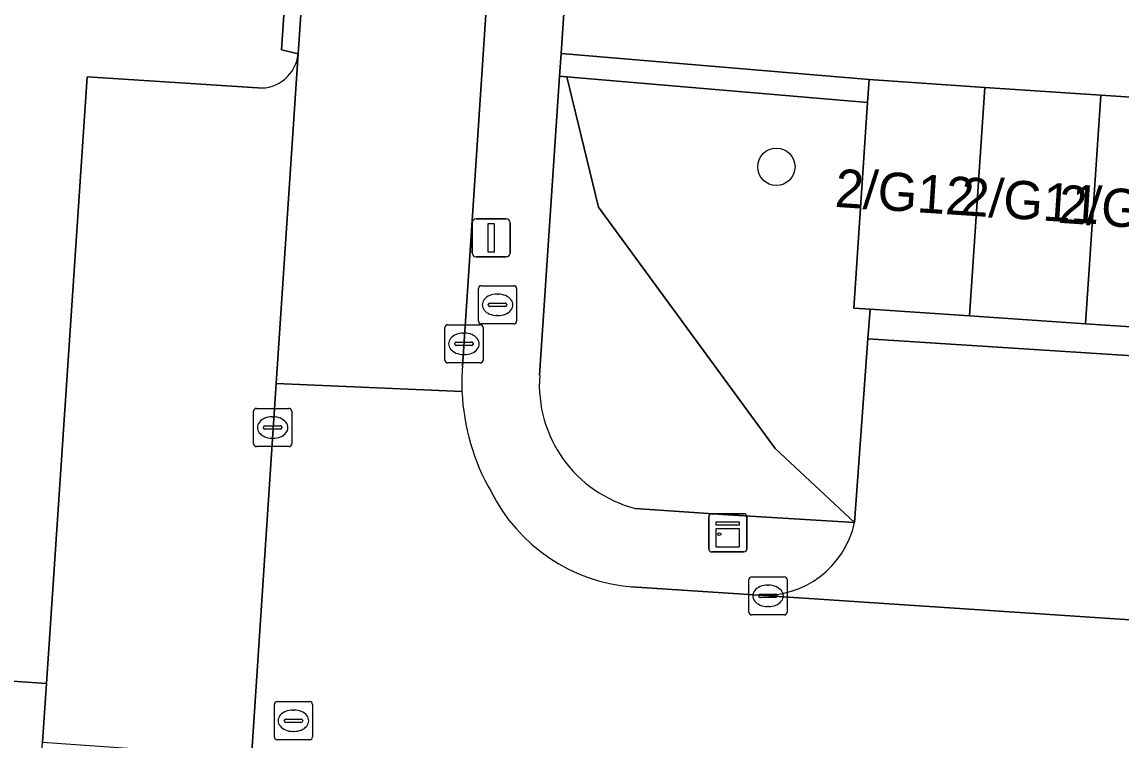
# Model space of a CAD drawing. Extents: x 161848 to 162726, y 385382 to 386521.
# Drawn here: x 161953.99 to 161982.82, y 386006.55 to 386025.38 of the extents above; entities that cross this region are included whole.
import ezdxf

# ---------------------------------------------------------------- set-up
doc = ezdxf.new("R2010")
doc.units = 0
for name, color, linetype in [('IMGEO_Boom', 7, 'Continuous'), ('IMGEO_Brandkraan', 7, 'Continuous'), ('IMGEO_Erf', 7, 'Continuous'), ('IMGEO_Groenvoorziening', 7, 'Continuous'), ('IMGEO_Haag', 7, 'Continuous'), ('IMGEO_Kast', 7, 'Continuous'), ('IMGEO_Kolk', 7, 'Continuous'), ('IMGEO_Lichtmast', 7, 'Continuous'), ('IMGEO_Pand', 7, 'Continuous'), ('IMGEO_Pand_nummerreeks', 7, 'Continuous'), ('IMGEO_Parkeervlak_open', 7, 'Continuous'), ('IMGEO_Rijbaan_lokaal_open', 7, 'Continuous'), ('IMGEO_Rioolput', 7, 'Continuous'), ('IMGEO_Verkeerseiland_open', 7, 'Continuous'), ('IMGEO_Voetpad_open', 7, 'Continuous')]:
    doc.layers.add(name, color=color, linetype=linetype)

msp = doc.modelspace()

# ---------------------------------------------------------------- linework, layer by layer
at = {"layer": 'IMGEO_Boom'}
msp.add_circle((161973.762, 386021.589), 0.489, dxfattribs=at)
at = {"layer": 'IMGEO_Brandkraan'}
for p, q in [((161965.952, 386017.547), (161965.952, 386018.399)), ((161966.027, 386018.473), (161966.879, 386018.473)), ((161966.953, 386018.399), (161966.953, 386017.547)), ((161966.254, 386018.016), (161966.652, 386018.016)), ((161966.44, 386018.253), (161966.465, 386018.253)), ((161966.211, 386017.967), (161966.211, 386017.979)), ((161966.649, 386017.93), (161966.251, 386017.93)), ((161966.695, 386017.979), (161966.695, 386017.967)), ((161966.879, 386017.473), (161966.027, 386017.473)), ((161966.463, 386017.693), (161966.438, 386017.693))]:
    msp.add_line(p, q, dxfattribs=at)
for points in [[(161965.952, 386017.547), (161965.952, 386018.399)], [(161966.027, 386018.473), (161966.879, 386018.473)], [(161966.953, 386018.399), (161966.953, 386017.547)], [(161966.879, 386017.473), (161966.027, 386017.473)]]:
    msp.add_lwpolyline(points, dxfattribs=at)
for centre, radius, start, end in [((161966.029, 386018.397), 0.0765, 91.552, 178.448), ((161966.029, 386018.397), 0.0765, 91.552, 178.448), ((161966.877, 386018.397), 0.0765, 1.552, 88.448), ((161966.877, 386018.397), 0.0765, 1.552, 88.448), ((161966.251, 386017.976), 0.0403, 85.8775, 175.7526), ((161966.656, 386017.978), 0.0386, 1.7309, 96.639), ((161966.248, 386017.966), 0.0366, 178.938, 274.7102), ((161966.652, 386017.973), 0.043, 264.8664, 352.4533), ((161966.029, 386017.549), 0.0765, 181.552, 268.448), ((161966.029, 386017.549), 0.0765, 181.552, 268.448), ((161966.877, 386017.549), 0.0765, 271.552, 358.448), ((161966.877, 386017.549), 0.0765, 271.552, 358.448)]:
    msp.add_arc(centre, radius, start, end, dxfattribs=at)
for centre, major_axis, ratio, start_param, end_param in [((161966.439, 386017.973), (-0.387, 0.002), 0.722429, 4.712389, 7.853982), ((161966.464, 386017.973), (-0.39, 0.002), 0.717154, 1.570796, 4.712389)]:
    msp.add_ellipse(centre, major_axis=major_axis, ratio=ratio, start_param=start_param, end_param=end_param, dxfattribs=at)
at = {"layer": 'IMGEO_Erf'}
msp.add_lwpolyline([(161973.071, 386098.474), (161968.121, 386024.56), (161976.193, 386023.874), (161979.229, 386023.67), (161982.266, 386023.466), (161985.302, 386023.262), (161988.338, 386023.059), (161991.375, 386022.855), (161994.411, 386022.651), (161994.699, 386027.79)], dxfattribs=at)
at = {"layer": 'IMGEO_Groenvoorziening'}
for points in [[(161943.048, 386128.27), (161942.06, 386112.903), (161936.093, 386020.157), (161930.341, 386020.536), (161932.562, 386055.006), (161928.781, 386055.255), (161926.803, 386025.337), (161926.763, 386019.638), (161926.902, 386014.485), (161927.435, 386010.565), (161928.183, 386010.091), (161929.03, 386009.835), (161934.854, 386009.415), (161936.618, 386009.293), (161937.077, 386015.948), (161946.906, 386015.3), (161946.445, 386008.616), (161954.625, 386008.052), (161955.692, 386023.943), (161960.168, 386023.656)], [(161961.227, 386024.551), (161960.785, 386024.65), (161965.608, 386096.137), (161966.064, 386096.102)], [(161969.103, 386020.53), (161968.271, 386023.945), (161968.081, 386023.961), (161967.557, 386016.132)], [(161970.064, 386012.641), (161972.489, 386012.469), (161975.811, 386012.268), (161973.729, 386014.209), (161969.103, 386020.53)]]:
    msp.add_lwpolyline(points, dxfattribs=at)
for points in [[(161968.121, 386024.56), (161968.081, 386023.961), (161968.271, 386023.945), (161976.153, 386023.275), (161976.193, 386023.874)], [(161976.153, 386023.275), (161968.271, 386023.945), (161969.103, 386020.53), (161973.729, 386014.209), (161975.811, 386012.268), (161976.163, 386017.082), (161976.22, 386017.858), (161975.791, 386017.887)]]:
    msp.add_lwpolyline(points, close=True, dxfattribs=at)
for centre, radius, start, end in [((161960.241, 386024.644), 0.99, 265.7686, 354.6362), ((161970.893, 386015.882), 3.345, 175.7137, 255.653)]:
    msp.add_arc(centre, radius, start, end, dxfattribs=at)
at = {"layer": 'IMGEO_Haag'}
msp.add_lwpolyline([(161968.121, 386024.56), (161968.081, 386023.961), (161968.271, 386023.945), (161976.153, 386023.275), (161976.193, 386023.874)], close=True, dxfattribs=at)
at = {"layer": 'IMGEO_Kast'}
for p, q in [((161971.988, 386011.575), (161971.988, 386012.416)), ((161971.988, 386012.416), (161971.988, 386011.575)), ((161972.063, 386012.5), (161972.904, 386012.5)), ((161972.904, 386012.5), (161972.063, 386012.5)), ((161972.988, 386012.425), (161972.988, 386011.584)), ((161972.988, 386011.584), (161972.988, 386012.425)), ((161972.913, 386011.5), (161972.072, 386011.5)), ((161972.072, 386011.5), (161972.913, 386011.5))]:
    msp.add_line(p, q, dxfattribs=at)
for points in [[(161972.183, 386012.29), (161972.783, 386012.29), (161972.783, 386012.205), (161972.183, 386012.205), (161972.183, 386012.29)], [(161972.183, 386012.115), (161972.783, 386012.115), (161972.783, 386011.626), (161972.183, 386011.626), (161972.183, 386012.115)]]:
    msp.add_lwpolyline(points, dxfattribs=at)
msp.add_circle((161972.267, 386011.964), 0.0377, dxfattribs=at)
for centre, start, end in [((161972.066, 386012.422), 92.4484, 184.2845), ((161972.066, 386012.422), 92.4484, 184.2845), ((161972.91, 386012.422), 2.4484, 94.2845), ((161972.91, 386012.422), 2.4484, 94.2845), ((161972.066, 386011.578), 182.4484, 274.2845), ((161972.066, 386011.578), 182.4484, 274.2845), ((161972.91, 386011.578), 272.4484, 4.2845), ((161972.91, 386011.578), 272.4484, 4.2845)]:
    msp.add_arc(centre, 0.0779, start, end, dxfattribs=at)
at = {"layer": 'IMGEO_Kolk'}
for p, q in [((161965.146, 386017.452), (161965.998, 386017.452)), ((161965.071, 386016.526), (161965.071, 386017.378)), ((161965.559, 386017.232), (161965.584, 386017.232)), ((161966.072, 386017.378), (161966.072, 386016.526)), ((161965.33, 386016.946), (161965.33, 386016.958)), ((161965.768, 386016.909), (161965.37, 386016.909)), ((161965.373, 386016.995), (161965.771, 386016.995)), ((161965.814, 386016.958), (161965.814, 386016.946)), ((161965.582, 386016.672), (161965.557, 386016.672)), ((161965.998, 386016.452), (161965.146, 386016.452)), ((161960.056, 386014.333), (161960.056, 386015.185)), ((161960.131, 386015.259), (161960.983, 386015.259)), ((161961.057, 386015.185), (161961.057, 386014.333)), ((161960.544, 386015.039), (161960.569, 386015.039)), ((161960.315, 386014.753), (161960.315, 386014.765)), ((161960.753, 386014.716), (161960.355, 386014.716)), ((161960.358, 386014.802), (161960.756, 386014.802)), ((161960.799, 386014.765), (161960.799, 386014.753)), ((161960.983, 386014.259), (161960.131, 386014.259)), ((161960.567, 386014.479), (161960.542, 386014.479)), ((161973.118, 386010.849), (161973.97, 386010.849)), ((161973.043, 386009.923), (161973.043, 386010.775)), ((161973.531, 386010.629), (161973.556, 386010.629)), ((161974.044, 386010.775), (161974.044, 386009.923)), ((161973.302, 386010.343), (161973.302, 386010.355)), ((161973.74, 386010.306), (161973.342, 386010.306)), ((161973.345, 386010.392), (161973.743, 386010.392)), ((161973.786, 386010.355), (161973.786, 386010.343)), ((161973.554, 386010.069), (161973.529, 386010.069)), ((161973.97, 386009.849), (161973.118, 386009.849))]:
    msp.add_line(p, q, dxfattribs=at)
for points in [[(161965.146, 386017.452), (161965.998, 386017.452)], [(161965.071, 386016.526), (161965.071, 386017.378)], [(161966.072, 386017.378), (161966.072, 386016.526)], [(161965.998, 386016.452), (161965.146, 386016.452)], [(161960.056, 386014.333), (161960.056, 386015.185)], [(161960.131, 386015.259), (161960.983, 386015.259)], [(161961.057, 386015.185), (161961.057, 386014.333)], [(161960.983, 386014.259), (161960.131, 386014.259)], [(161973.118, 386010.849), (161973.97, 386010.849)], [(161973.043, 386009.923), (161973.043, 386010.775)], [(161974.044, 386010.775), (161974.044, 386009.923)], [(161973.97, 386009.849), (161973.118, 386009.849)]]:
    msp.add_lwpolyline(points, dxfattribs=at)
for centre, radius, start, end in [((161965.148, 386017.376), 0.0765, 91.552, 178.448), ((161965.148, 386017.376), 0.0765, 91.552, 178.448), ((161965.996, 386017.376), 0.0765, 1.552, 88.448), ((161965.996, 386017.376), 0.0765, 1.552, 88.448), ((161965.37, 386016.955), 0.0403, 85.8775, 175.7526), ((161965.367, 386016.945), 0.0366, 178.938, 274.7102), ((161965.771, 386016.952), 0.043, 264.8664, 352.4533), ((161965.775, 386016.957), 0.0386, 1.7309, 96.639), ((161965.148, 386016.528), 0.0765, 181.552, 268.448), ((161965.148, 386016.528), 0.0765, 181.552, 268.448), ((161965.996, 386016.528), 0.0765, 271.552, 358.448), ((161965.996, 386016.528), 0.0765, 271.552, 358.448), ((161960.133, 386015.183), 0.0765, 91.552, 178.448), ((161960.133, 386015.183), 0.0765, 91.552, 178.448), ((161960.981, 386015.183), 0.0765, 1.552, 88.448), ((161960.981, 386015.183), 0.0765, 1.552, 88.448), ((161960.355, 386014.762), 0.0403, 85.8775, 175.7526), ((161960.352, 386014.752), 0.0366, 178.938, 274.7102), ((161960.756, 386014.759), 0.043, 264.8664, 352.4533), ((161960.76, 386014.764), 0.0386, 1.7309, 96.639), ((161960.133, 386014.335), 0.0765, 181.552, 268.448), ((161960.133, 386014.335), 0.0765, 181.552, 268.448), ((161960.981, 386014.335), 0.0765, 271.552, 358.448), ((161960.981, 386014.335), 0.0765, 271.552, 358.448), ((161973.12, 386010.773), 0.0765, 91.552, 178.448), ((161973.12, 386010.773), 0.0765, 91.552, 178.448), ((161973.968, 386010.773), 0.0765, 1.552, 88.448), ((161973.968, 386010.773), 0.0765, 1.552, 88.448), ((161973.342, 386010.352), 0.0403, 85.8775, 175.7526), ((161973.339, 386010.342), 0.0366, 178.938, 274.7102), ((161973.743, 386010.349), 0.043, 264.8664, 352.4533), ((161973.747, 386010.354), 0.0386, 1.7309, 96.639), ((161973.12, 386009.925), 0.0765, 181.552, 268.448), ((161973.12, 386009.925), 0.0765, 181.552, 268.448), ((161973.968, 386009.925), 0.0765, 271.552, 358.448), ((161973.968, 386009.925), 0.0765, 271.552, 358.448)]:
    msp.add_arc(centre, radius, start, end, dxfattribs=at)
for centre, major_axis, ratio, start_param, end_param in [((161965.558, 386016.952), (-0.387, 0.002), 0.722429, 4.712389, 7.853982), ((161965.583, 386016.952), (-0.39, 0.002), 0.717154, 1.570796, 4.712389), ((161960.543, 386014.759), (-0.387, 0.002), 0.722429, 4.712389, 7.853982), ((161960.568, 386014.759), (-0.39, 0.002), 0.717154, 1.570796, 4.712389), ((161973.53, 386010.349), (-0.387, 0.002), 0.722429, 4.712389, 7.853982), ((161973.555, 386010.349), (-0.39, 0.002), 0.717154, 1.570796, 4.712389)]:
    msp.add_ellipse(centre, major_axis=major_axis, ratio=ratio, start_param=start_param, end_param=end_param, dxfattribs=at)
at = {"layer": 'IMGEO_Lichtmast'}
for p, q in [((161965.791, 386019.328), (161965.791, 386020.128)), ((161965.791, 386020.128), (161965.791, 386019.328)), ((161965.891, 386020.228), (161966.681, 386020.228)), ((161966.681, 386020.228), (161965.891, 386020.228)), ((161966.781, 386020.128), (161966.781, 386019.328)), ((161966.781, 386019.328), (161966.781, 386020.128)), ((161966.681, 386019.228), (161965.891, 386019.228)), ((161965.891, 386019.228), (161966.681, 386019.228))]:
    msp.add_line(p, q, dxfattribs=at)
msp.add_lwpolyline([(161966.211, 386020.103), (161966.361, 386020.103), (161966.361, 386019.353), (161966.211, 386019.353), (161966.211, 386020.103)], dxfattribs=at)
for centre, start, end in [((161965.891, 386020.128), 90, 180), ((161965.891, 386020.128), 90, 180), ((161966.681, 386020.128), 0, 90), ((161966.681, 386020.128), 360, 90), ((161965.891, 386019.328), 180, 270), ((161965.891, 386019.328), 180, 270), ((161966.681, 386019.328), 270, 0), ((161966.681, 386019.328), 270, 0)]:
    msp.add_arc(centre, 0.1, start, end, dxfattribs=at)
at = {"layer": 'IMGEO_Pand'}
for points in [[(161979.229, 386023.67), (161976.193, 386023.874), (161976.153, 386023.275), (161975.791, 386017.887), (161976.22, 386017.858), (161978.827, 386017.683)], [(161981.864, 386017.479), (161982.266, 386023.466), (161979.229, 386023.67), (161978.827, 386017.683)], [(161984.9, 386017.275), (161985.302, 386023.262), (161982.266, 386023.466), (161981.864, 386017.479)]]:
    msp.add_lwpolyline(points, close=True, dxfattribs=at)
at = {"layer": 'IMGEO_Parkeervlak_open'}
for points in [[(161960.651, 386015.914), (161961.227, 386024.551)], [(161960.168, 386023.656), (161955.692, 386023.943), (161954.625, 386008.052), (161954.524, 386006.517), (161959.999, 386006.135), (161960.651, 386015.914)], [(162020.095, 386008.148), (162020.18, 386009.2), (162020.338, 386009.331), (162020.554, 386012.466), (162013.058, 386012.9), (162013.174, 386014.703), (162000, 386015.551), (161976.163, 386017.082), (161975.811, 386012.268)], [(161973.302, 386010.364), (162000, 386008.592), (162020.995, 386007.103)]]:
    msp.add_lwpolyline(points, dxfattribs=at)
for centre, radius, start, end in [((161960.241, 386024.644), 0.99, 265.7686, 354.6362), ((161973.436, 386012.793), 2.433, 266.8524, 347.535)]:
    msp.add_arc(centre, radius, start, end, dxfattribs=at)
at = {"layer": 'IMGEO_Rijbaan_lokaal_open'}
for points in [[(161970.952, 386098.074), (161966.224, 386098.31), (161966.064, 386096.102), (161961.227, 386024.551), (161960.651, 386015.914), (161965.521, 386015.701)], [(161965.532, 386016.361), (161970.952, 386098.074)], [(161965.521, 386015.701), (161960.651, 386015.914), (161959.999, 386006.135), (161970.104, 386005.509), (162000, 386003.528), (162022.818, 386001.933), (162023.151, 386006.999), (162020.995, 386007.103), (162000, 386008.592)], [(162000, 386008.592), (161973.302, 386010.364), (161969.967, 386010.585)]]:
    msp.add_lwpolyline(points, dxfattribs=at)
for centre, radius, start, end in [((161971.255, 386015.936), 5.739, 175.7481, 182.3422), ((161971.217, 386015.937), 5.701, 182.3684, 210.0815), ((161970.353, 386015.121), 4.552, 206.6497, 265.1413)]:
    msp.add_arc(centre, radius, start, end, dxfattribs=at)
at = {"layer": 'IMGEO_Rioolput'}
for p, q in [((161960.602, 386006.652), (161960.602, 386007.504)), ((161960.677, 386007.578), (161961.529, 386007.578)), ((161961.09, 386007.358), (161961.115, 386007.358)), ((161961.603, 386007.504), (161961.603, 386006.652)), ((161960.861, 386007.072), (161960.861, 386007.084)), ((161960.904, 386007.121), (161961.302, 386007.121)), ((161961.345, 386007.084), (161961.345, 386007.072)), ((161961.299, 386007.035), (161960.901, 386007.035)), ((161961.113, 386006.798), (161961.088, 386006.798)), ((161961.529, 386006.578), (161960.677, 386006.578))]:
    msp.add_line(p, q, dxfattribs=at)
for points in [[(161960.602, 386006.652), (161960.602, 386007.504)], [(161960.677, 386007.578), (161961.529, 386007.578)], [(161961.603, 386007.504), (161961.603, 386006.652)], [(161961.529, 386006.578), (161960.677, 386006.578)]]:
    msp.add_lwpolyline(points, dxfattribs=at)
for centre, radius, start, end in [((161960.679, 386007.502), 0.0765, 91.552, 178.448), ((161960.679, 386007.502), 0.0765, 91.552, 178.448), ((161961.527, 386007.502), 0.0765, 1.552, 88.448), ((161961.527, 386007.502), 0.0765, 1.552, 88.448), ((161960.901, 386007.081), 0.0403, 85.8775, 175.7526), ((161960.898, 386007.071), 0.0366, 178.938, 274.7102), ((161961.302, 386007.078), 0.043, 264.8664, 352.4533), ((161961.306, 386007.083), 0.0386, 1.7309, 96.639), ((161960.679, 386006.654), 0.0765, 181.552, 268.448), ((161960.679, 386006.654), 0.0765, 181.552, 268.448), ((161961.527, 386006.654), 0.0765, 271.552, 358.448), ((161961.527, 386006.654), 0.0765, 271.552, 358.448)]:
    msp.add_arc(centre, radius, start, end, dxfattribs=at)
for centre, major_axis, ratio, start_param, end_param in [((161961.089, 386007.078), (-0.387, 0.002), 0.722429, 4.712389, 7.853982), ((161961.114, 386007.078), (-0.39, 0.002), 0.717154, 1.570796, 4.712389)]:
    msp.add_ellipse(centre, major_axis=major_axis, ratio=ratio, start_param=start_param, end_param=end_param, dxfattribs=at)
at = {"layer": 'IMGEO_Verkeerseiland_open'}
msp.add_lwpolyline([(161965.608, 386096.137), (161960.785, 386024.65), (161961.227, 386024.551), (161966.064, 386096.102)], close=True, dxfattribs=at)
at = {"layer": 'IMGEO_Voetpad_open'}
for points in [[(161967.557, 386016.132), (161968.081, 386023.961), (161968.121, 386024.56), (161973.071, 386098.474), (161973.273, 386099.425)], [(161970.952, 386098.074), (161965.532, 386016.361)], [(161975.811, 386012.268), (161972.489, 386012.469), (161970.064, 386012.641)], [(161969.967, 386010.585), (161973.302, 386010.364)], [(161952.446, 386002.932), (161954.28, 386002.809), (161954.524, 386006.517), (161954.625, 386008.052), (161946.445, 386008.616)]]:
    msp.add_lwpolyline(points, dxfattribs=at)
msp.add_lwpolyline([(161976.163, 386017.082), (162000, 386015.551), (162013.174, 386014.703), (162013.217, 386015.376), (162010.676, 386015.546), (162007.643, 386015.749), (162004.61, 386015.952), (162001.578, 386016.155), (162000, 386016.261), (161998.545, 386016.359), (161995.511, 386016.562), (161994.009, 386016.664), (161990.973, 386016.868), (161987.936, 386017.072), (161984.9, 386017.275), (161981.864, 386017.479), (161978.827, 386017.683), (161976.22, 386017.858)], close=True, dxfattribs=at)
for centre, radius, start, end in [((161971.255, 386015.936), 5.739, 175.7481, 182.3422), ((161970.893, 386015.882), 3.345, 175.7137, 255.653), ((161971.217, 386015.937), 5.701, 182.3684, 210.0815), ((161970.353, 386015.121), 4.552, 206.6497, 265.1413), ((161973.436, 386012.793), 2.433, 266.8524, 347.535)]:
    msp.add_arc(centre, radius, start, end, dxfattribs=at)

# ---------------------------------------------------------------- texts
at = {"layer": 'IMGEO_Pand_nummerreeks'}
for s, rotation, p in [('2/G12', 356.2471, (161975.278, 386020.541)), ('2/G11', 356.2483, (161978.571, 386020.325)), ('2/G10', 356.2483, (161981.135, 386020.124))]:
    msp.add_text(s, height=1, rotation=rotation, dxfattribs=at).set_placement(p)

doc.saveas('drawing.dxf')
